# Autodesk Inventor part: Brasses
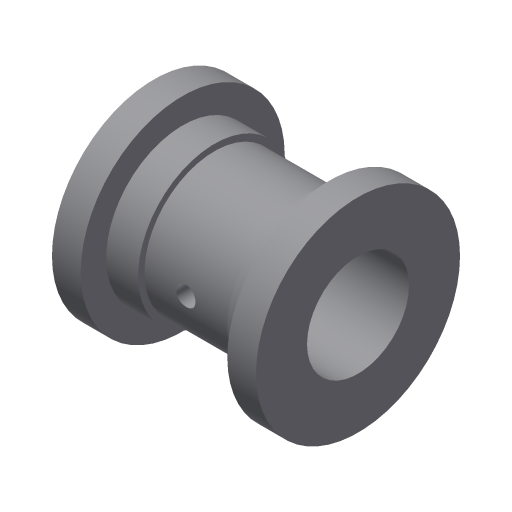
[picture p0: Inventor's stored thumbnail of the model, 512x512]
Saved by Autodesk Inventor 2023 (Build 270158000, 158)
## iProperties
Created: 2009-04
Part Number: Brasses
Document SubType Name: Modeling
Designer: Sham
Density: 1 g/cm^3
Material: Generic
Appearance: Default
Author: Sham
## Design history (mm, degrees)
sketch "Sketch1"
  geometry: L1 (0, 32)-(9, 32); L2 (0, 16)-(64, 16); L3 (64, 32)-(55, 32); L4 (55, 32)-(55, 24); L5 (55, 24)-(47, 24); L6 (19, 22)-(47, 22); L7 (47, 24)-(47, 22); L8 (19, 22)-(19, 24); L9 (19, 24)-(9, 24); L10 (9, 24)-(9, 32); L11 (0, 32)-(0, 16); L12 (64, 32)-(64, 16); L13 (-12.8, 0)-(76.8, 0) reference; 1 further point
  constraints: 24 end point, 7 parallel, 4 perpendicular, 1 collinear, 1 horizontal, 1 vertical alignment, 1 other
  dimensions: "d0" = 9 distance of L1.start L1.end; "d2" = 16 distance from line of L2 point (0, 0); "d3" = 64 distance of L2.start L2.end; "d4" = 24 distance from line of point (0, 0) L5; "d5" = 28 distance of L6.start L6.end; "d6" = 22 distance from line of point (0, 0) L6; "d7" = 8 distance of L4.end L5.end
revolve "Revolution1" sketch "Sketch1" stored, may be unused: angle "d8" = 90 deg
workplane "Work Plane1"
sketch "Sketch2"
  geometry: C1 r 4 at (-32, 0)
  constraints: 1 centre point
  dimensions: "d10" = 8 diameter of C1
extrude "Extrusion1" join sketch "Sketch2" stored distance "d11" = 10; taper "d12" = 0 deg
sketch "Sketch3"
  geometry: C1 r 4 at (0, 0) reference; C2 r 3 at (0, 0)
  constraints: 1 centre point, 1 coincident
  dimensions: "d13" = 6 diameter of C2
extrude "Extrusion2" cut sketch "Sketch3" extent not by distance; stored distance "d14" = 10; taper "d15" = 0 deg
body "Solid1"
